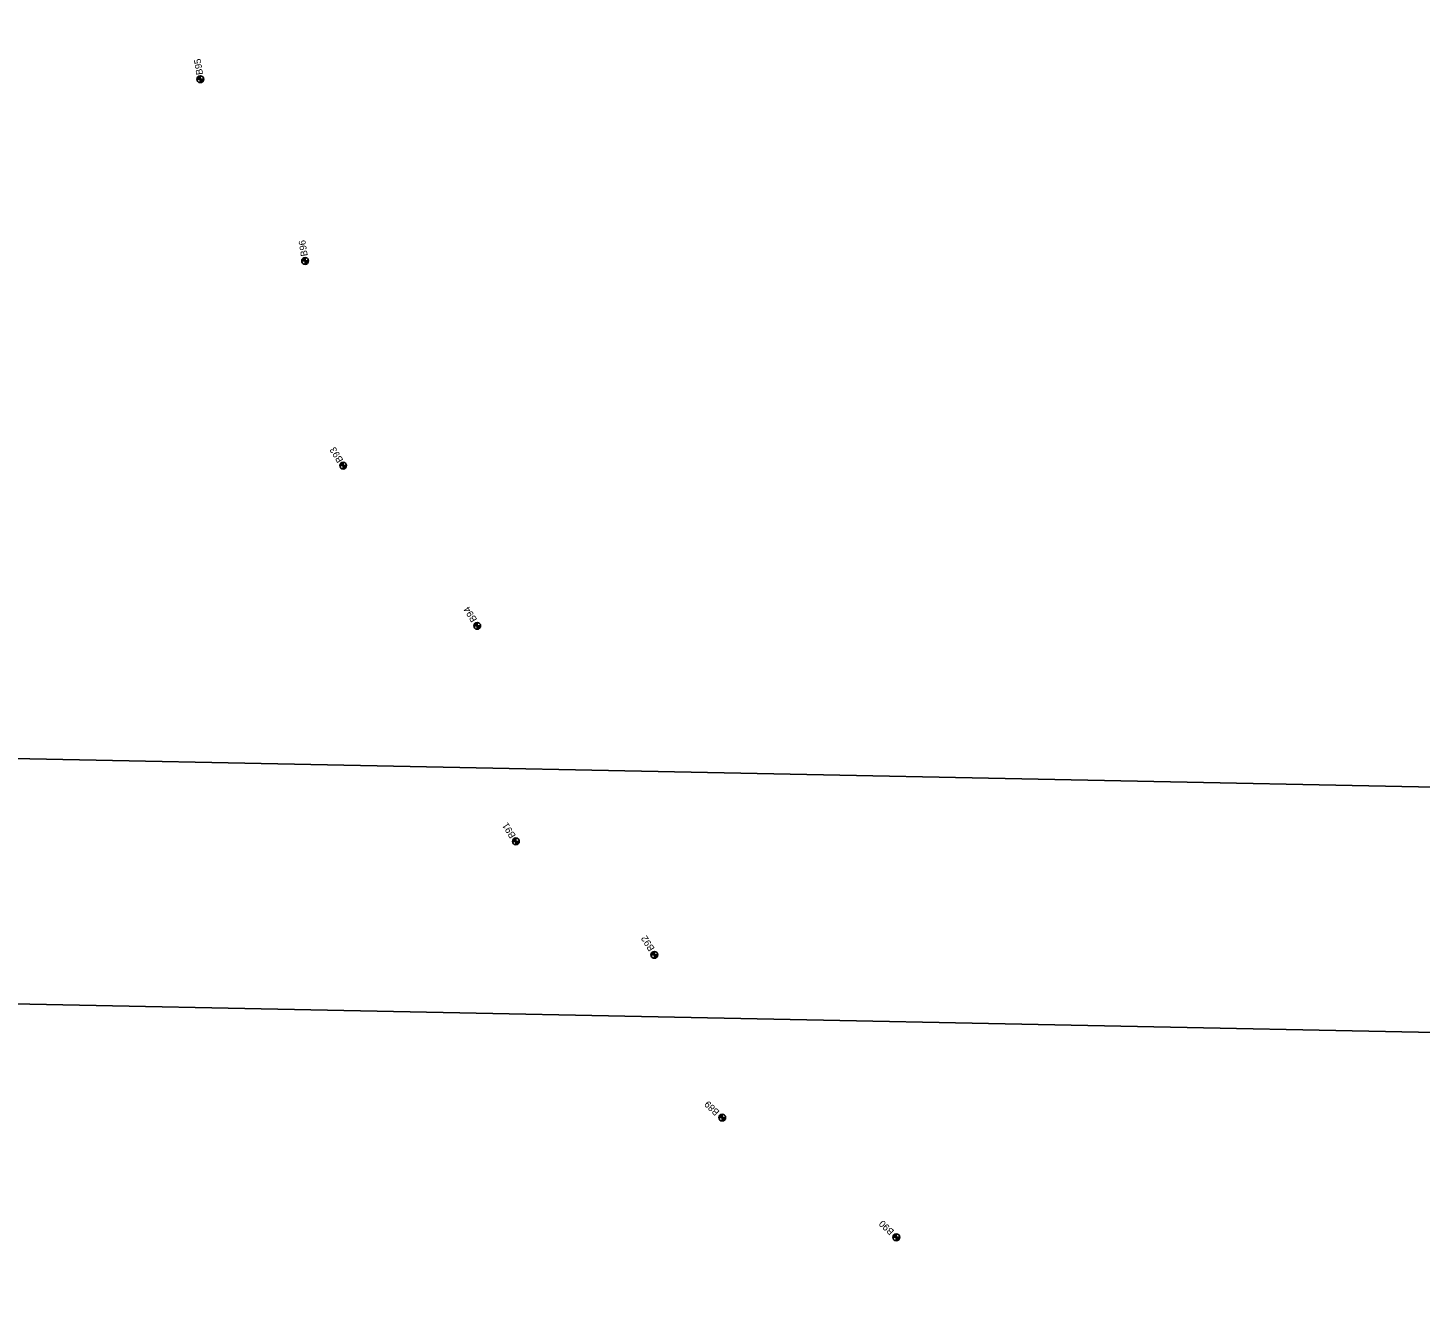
# Model space of a CAD drawing. Extents: x 345549 to 379569, y 127949 to 230467.
# Drawn here: x 355897 to 357938, y 178813 to 180701 of the extents above; entities that cross this region are included whole.
import ezdxf

# ---------------------------------------------------------------- set-up
doc = ezdxf.new("R2010")
doc.units = 0
for name, color, linetype in [('E_SOIL_BORE1 [KAPUR_CADDS_LEVELS]', 7, 'Continuous'), ('E_SOIL_BORE2 [KAPUR_CADDS_LEVELS]', 7, 'Continuous'), ('P_MARK', 7, 'Continuous'), ('P_RDWY_Text', 7, 'Continuous'), ('PLT_Sheet_Border', 7, 'Continuous')]:
    doc.layers.add(name, color=color, linetype=linetype)

msp = doc.modelspace()

# ---------------------------------------------------------------- linework, layer by layer
at = {"layer": 'P_MARK'}
for p, q in [((356144.6, 180626), (356154.6, 180626)), ((356149.6, 180631), (356149.6, 180621)), ((356298.3, 180359.4), (356308.3, 180359.4)), ((356303.3, 180364.4), (356303.3, 180354.4)), ((356354.1, 180059.1), (356364.1, 180059.1)), ((356359.1, 180064.1), (356359.1, 180054.1)), ((356555.7, 179829.1), (356555.7, 179819.1)), ((356550.7, 179824.1), (356560.7, 179824.1)), ((356607.4, 179508), (356617.4, 179508)), ((356612.4, 179513), (356612.4, 179503)), ((356810.5, 179341.5), (356820.5, 179341.5)), ((356815.5, 179346.5), (356815.5, 179336.5)), ((356910, 179102.8), (356920, 179102.8)), ((356915, 179107.8), (356915, 179097.8)), ((357170.2, 178932.2), (357170.2, 178922.2)), ((357165.2, 178927.2), (357175.2, 178927.2))]:
    msp.add_line(p, q, dxfattribs=at)
for centre in [(356149.6, 180626), (356303.3, 180359.4), (356359.1, 180059.1), (356555.7, 179824.1), (356612.4, 179508), (356815.5, 179341.5), (356915, 179102.8), (357170.2, 178927.2)]:
    msp.add_circle(centre, 5, dxfattribs=at)
for centre, radius, start, end in [((356149.6, 180626), 4.5, 89.9869, 179.9869), ((356149.6, 180626), 4, 89.9869, 179.9869), ((356149.6, 180626), 3.5, 89.9869, 179.9869), ((356149.6, 180626), 3, 89.9869, 179.9869), ((356149.6, 180626), 2.5, 89.9869, 179.9869), ((356149.6, 180626), 2, 89.9869, 179.9869), ((356149.6, 180626), 1.5, 89.9869, 179.9869), ((356149.6, 180626), 1, 89.9869, 179.9869), ((356149.6, 180626), 0.5, 89.9869, 179.9869), ((356149.6, 180626), 4.5, 269.9869, 359.9869), ((356149.6, 180626), 4, 269.9869, 359.9869), ((356149.6, 180626), 3.5, 269.9869, 359.9869), ((356149.6, 180626), 3, 269.9869, 359.9869), ((356149.6, 180626), 2.5, 269.9869, 359.9869), ((356149.6, 180626), 2, 269.9869, 359.9869), ((356149.6, 180626), 1.5, 269.9869, 359.9869), ((356149.6, 180626), 1, 269.9869, 359.9869), ((356149.6, 180626), 0.5, 269.9869, 359.9869), ((356303.3, 180359.4), 4.5, 89.9869, 179.9869), ((356303.3, 180359.4), 4, 89.9869, 179.9869), ((356303.3, 180359.4), 3.5, 89.9869, 179.9869), ((356303.3, 180359.4), 3, 89.9869, 179.9869), ((356303.3, 180359.4), 2.5, 89.9869, 179.9869), ((356303.3, 180359.4), 2, 89.9869, 179.9869), ((356303.3, 180359.4), 1.5, 89.9869, 179.9869), ((356303.3, 180359.4), 1, 89.9869, 179.9869), ((356303.3, 180359.4), 0.5, 89.9869, 179.9869), ((356303.3, 180359.4), 4.5, 269.9869, 359.9869), ((356303.3, 180359.4), 4, 269.9869, 359.9869), ((356303.3, 180359.4), 3.5, 269.9869, 359.9869), ((356303.3, 180359.4), 3, 269.9869, 359.9869), ((356303.3, 180359.4), 2.5, 269.9869, 359.9869), ((356303.3, 180359.4), 2, 269.9869, 359.9869), ((356303.3, 180359.4), 1.5, 269.9869, 359.9869), ((356303.3, 180359.4), 1, 269.9869, 359.9869), ((356303.3, 180359.4), 0.5, 269.9869, 359.9869), ((356359.1, 180059.1), 4.5, 89.9869, 179.9869), ((356359.1, 180059.1), 4, 89.9869, 179.9869), ((356359.1, 180059.1), 3.5, 89.9869, 179.9869), ((356359.1, 180059.1), 3, 89.9869, 179.9869), ((356359.1, 180059.1), 2.5, 89.9869, 179.9869), ((356359.1, 180059.1), 2, 89.9869, 179.9869), ((356359.1, 180059.1), 1.5, 89.9869, 179.9869), ((356359.1, 180059.1), 1, 89.9869, 179.9869), ((356359.1, 180059.1), 0.5, 89.9869, 179.9869), ((356359.1, 180059.1), 4.5, 269.9869, 359.9869), ((356359.1, 180059.1), 4, 269.9869, 359.9869), ((356359.1, 180059.1), 3.5, 269.9869, 359.9869), ((356359.1, 180059.1), 3, 269.9869, 359.9869), ((356359.1, 180059.1), 2.5, 269.9869, 359.9869), ((356359.1, 180059.1), 2, 269.9869, 359.9869), ((356359.1, 180059.1), 1.5, 269.9869, 359.9869), ((356359.1, 180059.1), 1, 269.9869, 359.9869), ((356359.1, 180059.1), 0.5, 269.9869, 359.9869), ((356555.7, 179824.1), 4.5, 89.9869, 179.9869), ((356555.7, 179824.1), 4, 89.9869, 179.9869), ((356555.7, 179824.1), 3.5, 89.9869, 179.9869), ((356555.7, 179824.1), 3, 89.9869, 179.9869), ((356555.7, 179824.1), 2.5, 89.9869, 179.9869), ((356555.7, 179824.1), 2, 89.9869, 179.9869), ((356555.7, 179824.1), 1.5, 89.9869, 179.9869), ((356555.7, 179824.1), 1, 89.9869, 179.9869), ((356555.7, 179824.1), 0.5, 89.9869, 179.9869), ((356555.7, 179824.1), 4.5, 269.9869, 359.9869), ((356555.7, 179824.1), 4, 269.9869, 359.9869), ((356555.7, 179824.1), 3.5, 269.9869, 359.9869), ((356555.7, 179824.1), 3, 269.9869, 359.9869), ((356555.7, 179824.1), 2.5, 269.9869, 359.9869), ((356555.7, 179824.1), 2, 269.9869, 359.9869), ((356555.7, 179824.1), 1.5, 269.9869, 359.9869), ((356555.7, 179824.1), 1, 269.9869, 359.9869), ((356555.7, 179824.1), 0.5, 269.9869, 359.9869), ((356612.4, 179508), 4.5, 89.9869, 179.9869), ((356612.4, 179508), 4, 89.9869, 179.9869), ((356612.4, 179508), 3.5, 89.9869, 179.9869), ((356612.4, 179508), 3, 89.9869, 179.9869), ((356612.4, 179508), 2.5, 89.9869, 179.9869), ((356612.4, 179508), 2, 89.9869, 179.9869), ((356612.4, 179508), 1.5, 89.9869, 179.9869), ((356612.4, 179508), 1, 89.9869, 179.9869), ((356612.4, 179508), 0.5, 89.9869, 179.9869), ((356612.4, 179508), 4.5, 269.9869, 359.9869), ((356612.4, 179508), 4, 269.9869, 359.9869), ((356612.4, 179508), 3.5, 269.9869, 359.9869), ((356612.4, 179508), 3, 269.9869, 359.9869), ((356612.4, 179508), 2.5, 269.9869, 359.9869), ((356612.4, 179508), 2, 269.9869, 359.9869), ((356612.4, 179508), 1.5, 269.9869, 359.9869), ((356612.4, 179508), 1, 269.9869, 359.9869), ((356612.4, 179508), 0.5, 269.9869, 359.9869), ((356815.5, 179341.5), 4.5, 89.9869, 179.9869), ((356815.5, 179341.5), 4, 89.9869, 179.9869), ((356815.5, 179341.5), 3.5, 89.9869, 179.9869), ((356815.5, 179341.5), 3, 89.9869, 179.9869), ((356815.5, 179341.5), 2.5, 89.9869, 179.9869), ((356815.5, 179341.5), 2, 89.9869, 179.9869), ((356815.5, 179341.5), 1.5, 89.9869, 179.9869), ((356815.5, 179341.5), 1, 89.9869, 179.9869), ((356815.5, 179341.5), 0.5, 89.9869, 179.9869), ((356815.5, 179341.5), 4.5, 269.9869, 359.9869), ((356815.5, 179341.5), 4, 269.9869, 359.9869), ((356815.5, 179341.5), 3.5, 269.9869, 359.9869), ((356815.5, 179341.5), 3, 269.9869, 359.9869), ((356815.5, 179341.5), 2.5, 269.9869, 359.9869), ((356815.5, 179341.5), 2, 269.9869, 359.9869), ((356815.5, 179341.5), 1.5, 269.9869, 359.9869), ((356815.5, 179341.5), 1, 269.9869, 359.9869), ((356815.5, 179341.5), 0.5, 269.9869, 359.9869), ((356915, 179102.8), 4.5, 89.9869, 179.9869), ((356915, 179102.8), 4, 89.9869, 179.9869), ((356915, 179102.8), 3.5, 89.9869, 179.9869), ((356915, 179102.8), 3, 89.9869, 179.9869), ((356915, 179102.8), 2.5, 89.9869, 179.9869), ((356915, 179102.8), 2, 89.9869, 179.9869), ((356915, 179102.8), 1.5, 89.9869, 179.9869), ((356915, 179102.8), 1, 89.9869, 179.9869), ((356915, 179102.8), 0.5, 89.9869, 179.9869), ((356915, 179102.8), 4.5, 269.9869, 359.9869), ((356915, 179102.8), 4, 269.9869, 359.9869), ((356915, 179102.8), 3.5, 269.9869, 359.9869), ((356915, 179102.8), 3, 269.9869, 359.9869), ((356915, 179102.8), 2.5, 269.9869, 359.9869), ((356915, 179102.8), 2, 269.9869, 359.9869), ((356915, 179102.8), 1.5, 269.9869, 359.9869), ((356915, 179102.8), 1, 269.9869, 359.9869), ((356915, 179102.8), 0.5, 269.9869, 359.9869), ((357170.2, 178927.2), 4.5, 89.9869, 179.9869), ((357170.2, 178927.2), 4, 89.9869, 179.9869), ((357170.2, 178927.2), 3.5, 89.9869, 179.9869), ((357170.2, 178927.2), 3, 89.9869, 179.9869), ((357170.2, 178927.2), 2.5, 89.9869, 179.9869), ((357170.2, 178927.2), 2, 89.9869, 179.9869), ((357170.2, 178927.2), 1.5, 89.9869, 179.9869), ((357170.2, 178927.2), 1, 89.9869, 179.9869), ((357170.2, 178927.2), 0.5, 89.9869, 179.9869), ((357170.2, 178927.2), 4.5, 269.9869, 359.9869), ((357170.2, 178927.2), 4, 269.9869, 359.9869), ((357170.2, 178927.2), 3.5, 269.9869, 359.9869), ((357170.2, 178927.2), 3, 269.9869, 359.9869), ((357170.2, 178927.2), 2.5, 269.9869, 359.9869), ((357170.2, 178927.2), 2, 269.9869, 359.9869), ((357170.2, 178927.2), 1.5, 269.9869, 359.9869), ((357170.2, 178927.2), 1, 269.9869, 359.9869), ((357170.2, 178927.2), 0.5, 269.9869, 359.9869)]:
    msp.add_arc(centre, radius, start, end, dxfattribs=at)
at = {"layer": 'P_RDWY_Text'}
msp.add_lwpolyline([(345549, 179477.5), (346575.9, 230467.1), (379569.2, 229802.6), (378542.3, 178813)], close=True, dxfattribs=at)
at = {"layer": 'PLT_Sheet_Border'}
for points in [[(378542.3, 178813), (379569.2, 229802.6), (346575.9, 230467.1), (345549, 179477.5)], [(377799.7, 179188), (378799.5, 228827.9), (347305.8, 229462.2), (346306.1, 179822.3)]]:
    msp.add_lwpolyline(points, close=True, dxfattribs=at)

# ---------------------------------------------------------------- texts
at = {"layer": 'E_SOIL_BORE1 [KAPUR_CADDS_LEVELS]'}
for s, rotation, p in [('B95', 98.957, (356153.7, 180633.1)), ('B89', 136.1942, (356911.8, 179111.8)), ('B90', 136.1942, (357167.8, 178936.6))]:
    msp.add_text(s, height=10, rotation=rotation, dxfattribs=at).set_placement(p)
at = {"layer": 'E_SOIL_BORE2 [KAPUR_CADDS_LEVELS]'}
for s, rotation, p in [('B96', 98.957, (356307.2, 180367)), ('B93', 121.7799, (356359.7, 180067.3)), ('B94', 121.7799, (356556, 179833.4)), ('B91', 121.7799, (356612.7, 179516.4)), ('B92', 121.7799, (356816.3, 179350.8))]:
    msp.add_text(s, height=10, rotation=rotation, dxfattribs=at).set_placement(p)

doc.saveas('drawing.dxf')
